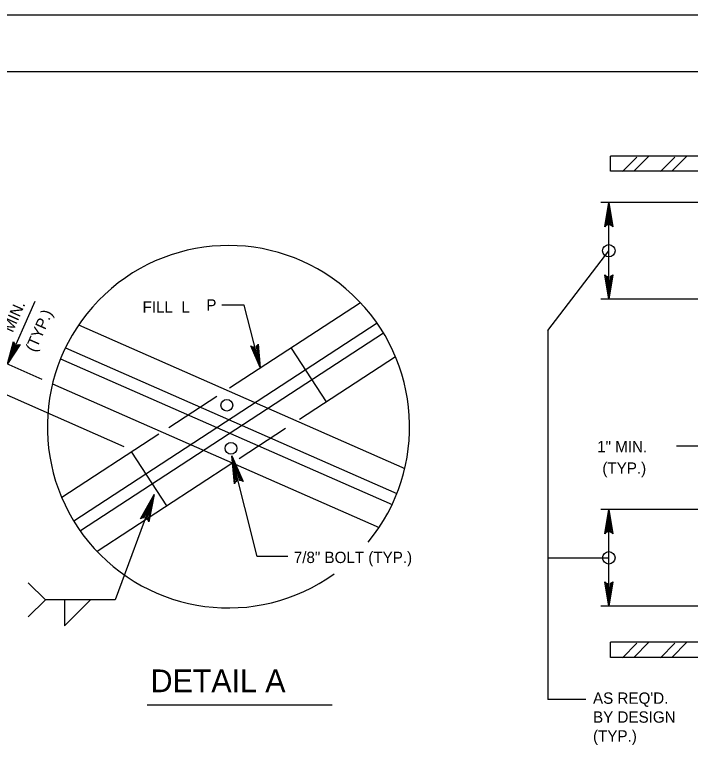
# Model space of a CAD drawing. Extents: x 634656 to 641360, y 298715 to 301183.
# Drawn here: x 638525.1 to 638703.8, y 300310.7 to 300507 of the extents above; entities that cross this region are included whole.
import ezdxf

# ---------------------------------------------------------------- set-up
doc = ezdxf.new("R2010")
doc.units = 0
for name, color, linetype in [('1', 7, 'Continuous'), ('2', 7, 'Continuous'), ('PLT-BNDY', 7, 'Continuous')]:
    doc.layers.add(name, color=color, linetype=linetype)

msp = doc.modelspace()

# ---------------------------------------------------------------- linework, layer by layer
at = {"layer": '1'}
for p, q in [((638737.5, 300469.62), (638682.69, 300469.62)), ((638682.69, 300465.62), (638682.69, 300469.62)), ((638689.66, 300469.34), (638685.85, 300465.53)), ((638692.86, 300469.62), (638688.86, 300465.62)), ((638699.69, 300469.34), (638695.88, 300465.53)), ((638702.89, 300469.62), (638698.9, 300465.62)), ((638737.5, 300465.62), (638682.69, 300465.62)), ((638733.41, 300457.39), (638680.14, 300457.39)), ((638682.25, 300431.82), (638682.25, 300457.39)), ((638666.15, 300423.48), (638682.25, 300444.61)), ((638523.21, 300414.67), (638530.52, 300431.28)), ((638616.58, 300430.86), (638581.93, 300408.27)), ((638733.41, 300431.82), (638680.14, 300431.82)), ((638590, 300413.76), (638585.82, 300430.26)), ((638620.97, 300425.44), (638540.74, 300373.14)), ((638542.01, 300424.99), (638628.26, 300387.03)), ((638622.68, 300422.81), (638542.46, 300370.52)), ((638538.52, 300418.95), (638626.16, 300380.38)), ((638598.2, 300418.88), (638607.49, 300404.63)), ((638521.07, 300415.62), (638532.29, 300410.68)), ((638537.25, 300416.07), (638624.91, 300377.5)), ((638625.83, 300416.58), (638600.43, 300400.02)), ((638535.1, 300409.44), (638621.46, 300371.43)), ((638517.87, 300408.69), (638553.93, 300392.82)), ((638578.54, 300406.06), (638565.85, 300397.8)), ((638596.71, 300397.6), (638584.46, 300389.61)), ((638563.23, 300396.09), (638537.55, 300379.35)), ((638555.99, 300391.37), (638565.28, 300377.12)), ((638589.27, 300363.76), (638582.7, 300389.67)), ((638582.49, 300388.33), (638546.88, 300365.12)), ((638562, 300380.2), (638551.71, 300352.31)), ((638733.54, 300376.21), (638680.14, 300376.21)), ((638682.25, 300350.64), (638682.25, 300376.21)), ((638666.15, 300363.43), (638682.25, 300363.43)), ((638551.71, 300352.31), (638533.25, 300352.31)), ((638733.54, 300350.64), (638680.14, 300350.64)), ((638737.5, 300341.09), (638682.69, 300341.09)), ((638682.69, 300337.09), (638682.69, 300341.09)), ((638689.66, 300340.81), (638685.85, 300337)), ((638692.86, 300341.09), (638688.86, 300337.09)), ((638699.69, 300340.81), (638695.88, 300337)), ((638702.89, 300341.09), (638698.9, 300337.09)), ((638737.5, 300337.09), (638682.69, 300337.09))]:
    msp.add_line(p, q, dxfattribs=at)
for points in [[(638681.48, 300451.26), (638681.93, 300451.49), (638682.25, 300457.39), (638681.48, 300451.26), (638681.21, 300450.95), (638682.25, 300457.39), (638682.54, 300451.49), (638682.98, 300451.28), (638682.25, 300457.39), (638683.28, 300450.95), (638682.98, 300451.28)], [(638683.02, 300437.95), (638682.58, 300437.72), (638682.25, 300431.82), (638683.02, 300437.95), (638683.29, 300438.27), (638682.25, 300431.82), (638681.96, 300437.72), (638681.52, 300437.93), (638682.25, 300431.82), (638681.23, 300438.27), (638681.52, 300437.93)], [(638526.21, 300419.69), (638525.74, 300419.66), (638523.21, 300414.67), (638526.21, 300419.69), (638526.57, 300419.86), (638523.21, 300414.67), (638525.21, 300419.89), (638524.91, 300420.24), (638523.21, 300414.67), (638524.78, 300420.64), (638524.91, 300420.24)], [(638589.28, 300419.56), (638588.93, 300419.25), (638590, 300413.76), (638589.28, 300419.56), (638589.46, 300419.91), (638590, 300413.76), (638588.36, 300419.1), (638587.91, 300419.2), (638590, 300413.76), (638587.57, 300419.44), (638587.91, 300419.2)], [(638583.43, 300383.4), (638583.85, 300383.77), (638582.52, 300390.35), (638583.43, 300383.4), (638583.22, 300382.97), (638582.52, 300390.35), (638584.53, 300383.96), (638585.07, 300383.84), (638582.52, 300390.35), (638585.49, 300383.56), (638585.07, 300383.84)], [(638558.77, 300373.97), (638559.34, 300374.04), (638562, 300380.2), (638558.77, 300373.97), (638558.36, 300373.74), (638562, 300380.2), (638560, 300373.8), (638560.38, 300373.4), (638562, 300380.2), (638560.56, 300372.93), (638560.38, 300373.4)], [(638681.48, 300370.08), (638681.93, 300370.31), (638682.25, 300376.21), (638681.48, 300370.08), (638681.21, 300369.76), (638682.25, 300376.21), (638682.54, 300370.31), (638682.98, 300370.1), (638682.25, 300376.21), (638683.28, 300369.76), (638682.98, 300370.1)], [(638683.02, 300356.77), (638682.58, 300356.54), (638682.25, 300350.64), (638683.02, 300356.77), (638683.29, 300357.09), (638682.25, 300350.64), (638681.96, 300356.54), (638681.52, 300356.75), (638682.25, 300350.64), (638681.23, 300357.09), (638681.52, 300356.75)]]:
    msp.add_lwpolyline(points, dxfattribs=at)
for centre, radius in [((638682.25, 300444.61), 1.65), ((638581.21, 300403.77), 1.55), ((638582.3, 300392.38), 1.55), ((638682.25, 300363.43), 1.65)]:
    msp.add_circle(centre, radius, dxfattribs=at)
msp.add_arc((638581.64, 300398.08), 47.91, 320.4277, 305.7025, dxfattribs=at)
at = {"layer": '2'}
for p, q in [((638256.43, 300491.99), (639042.43, 300491.99)), ((638585.82, 300430.26), (638579.85, 300430.26)), ((638666.15, 300423.48), (638666.15, 300325.95)), ((638711.59, 300392.95), (638700.14, 300392.95)), ((638597.37, 300363.76), (638589.27, 300363.76)), ((638538.26, 300352.31), (638538.26, 300345.42)), ((638538.26, 300345.42), (638545.15, 300352.31)), ((638676.17, 300325.95), (638666.15, 300325.95)), ((638560.13, 300324.58), (638609.06, 300324.58))]:
    msp.add_line(p, q, dxfattribs=at)
msp.add_lwpolyline([(638528.62, 300356.82), (638533.25, 300352.31), (638528.62, 300347.79)], dxfattribs=at)
at = {"layer": 'PLT-BNDY'}
msp.add_lwpolyline([(638216.43, 300506.99), (639057.43, 300506.99), (639057.43, 299912.99), (638216.43, 299912.99)], close=True, dxfattribs=at)

# ---------------------------------------------------------------- texts
at = {"layer": '1'}
for s, height, p in [('FILL  L', 3, (638558.91, 300428.23)), ('P', 3, (638575.78, 300428.77)), ('1" MIN.', 3, (638679.16, 300391.32)), ('7/8" BOLT (TYP.)', 2.9999, (638598.92, 300362.03)), ("AS REQ'D.", 3, (638678.07, 300324.82)), ('BY DESIGN', 3, (638678.07, 300319.82)), ('(TYP.)', 3, (638678.07, 300314.82))]:
    msp.add_text(s, height=height, dxfattribs=at).set_placement(p)
for s, p in [('MIN.', (638524.56, 300422.81)), ('(TYP.)', (638530.54, 300417.62))]:
    msp.add_text(s, height=3, rotation=66.2458, dxfattribs=at).set_placement(p)
at = {"layer": '2'}
for s, height, p in [('(TYP.)', 3, (638680.54, 300385.64)), ('DETAIL A', 6, (638561.06, 300327.89))]:
    msp.add_text(s, height=height, dxfattribs=at).set_placement(p)

doc.saveas('drawing.dxf')
